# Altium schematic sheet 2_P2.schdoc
size 309 x 223 mm; Symbol: Sheet-Symbol_A4; Device: Sheet-Symbol_A4; @Page Name: P2; @Create Date: 2023-04-30; @Page Count: 2; @Page No: 2; @Project Name: ESP32 Board V4.0; @Schematic Name: Schematic2_1; @Update Date: 2023-04-30; Company: 嘉立创EDA; Page Size: A4; Version: V1.0
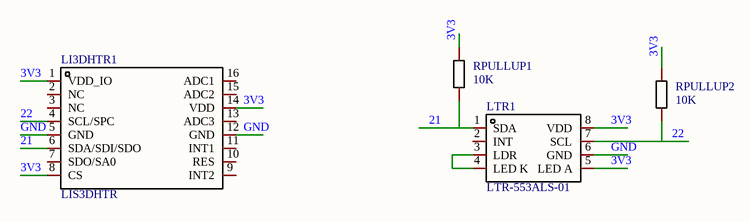
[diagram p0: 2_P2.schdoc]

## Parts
LI3DHTR1  LIS3DHTR  [LGA-16_L3.0-W3.0-P0.50-TL]
LTR1  LTR-553ALS-01  [SENSOR-SMD_L3.9-W2.4-P0.95-BL]
RPULLUP1  10K  [R0603]
RPULLUP2  10K  [R0603]

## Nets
3V3: LI3DHTR1.1(VDD_IO) LI3DHTR1.8(CS) LI3DHTR1.14(VDD) LTR1.5(LED_A) LTR1.8(VDD) RPULLUP1.2 RPULLUP2.2
21: LI3DHTR1.6(SDA/SDI/SDO) LTR1.1(SDA) RPULLUP1.1
22: LI3DHTR1.4(SCL/SPC) LTR1.7(SCL) RPULLUP2.1
GND: LI3DHTR1.5(GND) LI3DHTR1.12(GND) LTR1.6(GND)
NetLTR1_3: LTR1.3(LDR) LTR1.4(LED_K)

Not connected (* = marked no-connect by the designer): LI3DHTR1 2(NC) 3(NC) 7(SDO/SA0) 9(INT2) 10(RES) 11(INT1) 13(ADC3) 15(ADC2) 16(ADC1); LTR1 2(INT)

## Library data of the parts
LI3DHTR1 = LIS3DHTR: MEMS数字输出运动传感器，超低功耗高性能3轴加速度计“纳米”; Manufacturer: ST(意法半导体); Symbol: LIS3DHTR_C15134; Add into BOM: yes
LTR1 = LTR-553ALS-01: Manufacturer: LITEON(光宝); Add into BOM: yes
RPULLUP1 RPULLUP2 = Res_0603: Symbol: 电阻; Convert to PCB: yes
